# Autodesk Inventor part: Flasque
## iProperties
Author: Philippe
Shininess: 20.0
Angle Display Precision: 2
Document Length Units: 11269
Document Angle Units: 11283
Document Time Units: 11279
Document Mass Units: 11290
Document Length Units Precision: 3
Document Angle Units Precision: 2
Compacted: False
PropertySet Name: _Private Model Information
Created: 2002-06
Part Number: Flasque
Material: A-S13
Document SubType Name: Modélisation
Designer: Philippe
Control State: 0
Master: False
Checked Out: False
PropertySet Name: Design Tracking Control
Density: 0.0
Volumn: 0.0
Area: 0.0
PropertySet Name: Model Information
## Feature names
1. Extrusion1:Carré
2. Extrusion2:Centrage
3. Perçage1:Fixation [Hole]
4. Congé1:Angles carré [Fillet]
5. Extrusion4:Alvéole
6. Réseau circulaire1:Alvéoles [Circular Pattern]
7. Révolution1:Creusure centrage [Revolution]
8. Chanfrein1:Carré avant [Chamfer]
9. Chanfrein2:Perçages Fixation [Chamfer]
10. Chanfrein3:Carré arrière [Chamfer]
11. Extrusion5:Cylindre
12. Perçage2:Assemblage [Hole]
13. Extrusion6:Collerette extérieure
14. Révolution2:Cavité intérieure [Revolution]
15. Extrusion7:Dégagement vis
16. Extrusion8:Bossage vis
17. Réseau circulaire2:Dégagement et bossage [Circular Pattern]
18. Perçage3:Logement roulement [Hole]
19. Extrusion9:Perçage central
20. Chanfrein5:Portée roulement [Chamfer]
